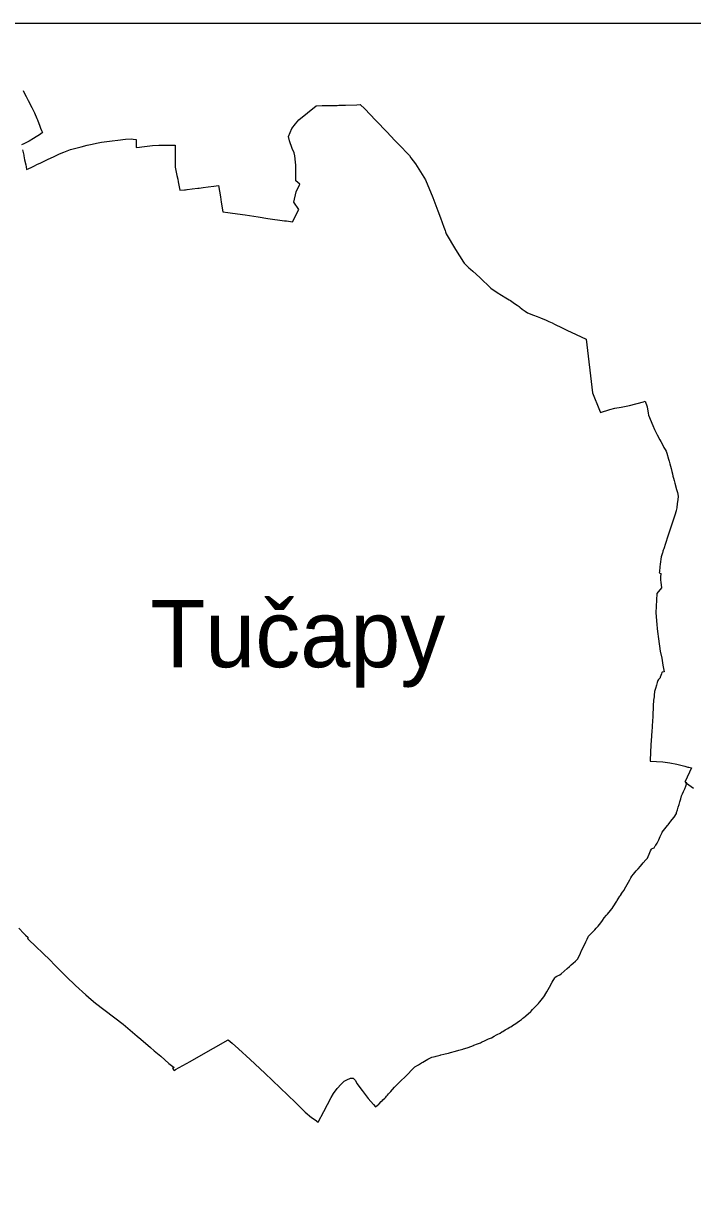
# Model space of a CAD drawing. Extents: x -552716 to -540720, y -1192685 to -1177912.
# Drawn here: x -547852 to -546493, y -1183546 to -1181162 of the extents above; entities that cross this region are included whole.
import ezdxf

# ---------------------------------------------------------------- set-up
doc = ezdxf.new("R2010")
doc.units = 0
doc.layers.add('Vrstva 1', color=7, linetype='Continuous')
doc.layers.add('Vrstva 60', color=7, linetype='Continuous')

msp = doc.modelspace()

# ---------------------------------------------------------------- linework, layer by layer
at = {"layer": 'Vrstva 1'}
for p, q in [((-546507.5, -1182701.9), (-546504.1, -1182704.7)), ((-546505.2, -1182707.5), (-546507.5, -1182701.9)), ((-546504.1, -1182704.7), (-546504.7, -1182705.9)), ((-546514.7, -1182731.2), (-546513.9, -1182728.6)), ((-546513.9, -1182728.6), (-546513.3, -1182727.3)), ((-546513.3, -1182727.3), (-546511, -1182722.2)), ((-546511, -1182722.2), (-546509.7, -1182719.6)), ((-546509.7, -1182719.6), (-546508.5, -1182717)), ((-546508.5, -1182717), (-546506.5, -1182711.8)), ((-546506.5, -1182711.8), (-546505.2, -1182707.5)), ((-546504.7, -1182705.9), (-546490.6, -1182715.5)), ((-546521.8, -1182754.7), (-546520, -1182748.9)), ((-546520, -1182748.9), (-546518.4, -1182743.6)), ((-546518.4, -1182743.6), (-546516.6, -1182737.4)), ((-546516.6, -1182737.4), (-546514.7, -1182731.2)), ((-546536.4, -1182782.7), (-546530.8, -1182775.4)), ((-546530.8, -1182775.4), (-546530.1, -1182774.6)), ((-546530.1, -1182774.6), (-546525.5, -1182767.1)), ((-546525.5, -1182767.1), (-546525, -1182765.5)), ((-546525, -1182765.5), (-546523.3, -1182759.8)), ((-546523.3, -1182759.8), (-546521.8, -1182754.7)), ((-546554.3, -1182805.4), (-546548.8, -1182798.5)), ((-546548.8, -1182798.5), (-546546.1, -1182795.1)), ((-546546.1, -1182795.1), (-546543.2, -1182791.4)), ((-546543.2, -1182791.4), (-546542.4, -1182790.5)), ((-546542.4, -1182790.5), (-546538.4, -1182785.2)), ((-546538.4, -1182785.2), (-546536.4, -1182782.7)), ((-546564, -1182826.5), (-546561.3, -1182820.6)), ((-546561.3, -1182820.6), (-546558.2, -1182814)), ((-546558.2, -1182814), (-546554.5, -1182805.9)), ((-546554.5, -1182805.9), (-546554.3, -1182805.4)), ((-546580.9, -1182850), (-546579.5, -1182846.7)), ((-546579.5, -1182846.7), (-546577.8, -1182843)), ((-546577.8, -1182843), (-546576.1, -1182839.9)), ((-546576.1, -1182839.9), (-546574.6, -1182838.4)), ((-546574.6, -1182838.4), (-546570.4, -1182836.8)), ((-546570.4, -1182836.8), (-546568.2, -1182832.8)), ((-546568.2, -1182832.8), (-546567.4, -1182831.5)), ((-546567.4, -1182831.5), (-546564.5, -1182827.2)), ((-546564.5, -1182827.2), (-546564, -1182826.5)), ((-546598.4, -1182874.2), (-546595.4, -1182870.6)), ((-546595.4, -1182870.6), (-546592.7, -1182867.5)), ((-546592.7, -1182867.5), (-546587.6, -1182861.6)), ((-546587.6, -1182861.6), (-546584.4, -1182857.9)), ((-546584.4, -1182857.9), (-546582.8, -1182854.4)), ((-546582.8, -1182854.4), (-546580.9, -1182850)), ((-546618, -1182898.2), (-546616, -1182894.6)), ((-546616, -1182894.6), (-546612.3, -1182890.3)), ((-546612.3, -1182890.3), (-546606.9, -1182884)), ((-546606.9, -1182884), (-546604.9, -1182881.7)), ((-546604.9, -1182881.7), (-546603.1, -1182879.6)), ((-546603.1, -1182879.6), (-546598.4, -1182874.2)), ((-546631, -1182921.3), (-546625.3, -1182911.2)), ((-546625.3, -1182911.2), (-546620, -1182901.8)), ((-546620, -1182901.8), (-546618, -1182898.2)), ((-546645.7, -1182944.3), (-546643.5, -1182940.9)), ((-546643.5, -1182940.9), (-546640, -1182935.5)), ((-546640, -1182935.5), (-546638.9, -1182933.8)), ((-546638.9, -1182933.8), (-546637.7, -1182931.9)), ((-546637.7, -1182931.9), (-546637.3, -1182931.3)), ((-546637.3, -1182931.3), (-546636, -1182929.2)), ((-546636, -1182929.2), (-546634.7, -1182927.2)), ((-546634.7, -1182927.2), (-546631.8, -1182922.9)), ((-546631.8, -1182922.9), (-546631, -1182921.3)), ((-546665.4, -1182971.9), (-546659.3, -1182964.4)), ((-546659.3, -1182964.4), (-546656.8, -1182961.2)), ((-546656.8, -1182961.2), (-546655.9, -1182960.1)), ((-546655.9, -1182960.1), (-546653.7, -1182956.8)), ((-546653.7, -1182956.8), (-546646.3, -1182945.2)), ((-546646.3, -1182945.2), (-546645.7, -1182944.3)), ((-546684.6, -1182996.5), (-546678.7, -1182989.4)), ((-546678.7, -1182989.4), (-546675.5, -1182984.6)), ((-546675.5, -1182984.6), (-546672.1, -1182979.6)), ((-546672.1, -1182979.6), (-546667.3, -1182974.1)), ((-546667.3, -1182974.1), (-546665.4, -1182971.9)), ((-547861.3, -1183000.1), (-547851.6, -1183011.3)), ((-547851.6, -1183011.3), (-547848.3, -1183014.2)), ((-547848.3, -1183014.2), (-547842.6, -1183019.2)), ((-546703.8, -1183016.3), (-546697.5, -1183009.8)), ((-546697.5, -1183009.8), (-546691.2, -1183003.4)), ((-546691.2, -1183003.4), (-546688.4, -1183000.5)), ((-546688.4, -1183000.5), (-546685.8, -1182997.8)), ((-546685.8, -1182997.8), (-546684.6, -1182996.5)), ((-547842.6, -1183019.2), (-547843.9, -1183021.1)), ((-547843.9, -1183021.1), (-547841.9, -1183023)), ((-547841.9, -1183023), (-547798, -1183065.5)), ((-546715.6, -1183040.9), (-546713.2, -1183035.9)), ((-546713.2, -1183035.9), (-546710.3, -1183030)), ((-546710.3, -1183030), (-546709.5, -1183028.2)), ((-546709.5, -1183028.2), (-546706.7, -1183022.4)), ((-546706.7, -1183022.4), (-546703.8, -1183016.3)), ((-546726.2, -1183063.2), (-546722.5, -1183055.5)), ((-546722.5, -1183055.5), (-546720.3, -1183050.8)), ((-546720.3, -1183050.8), (-546717.9, -1183045.8)), ((-546717.9, -1183045.8), (-546715.6, -1183040.9)), ((-547798, -1183065.5), (-547789.1, -1183075)), ((-547789.1, -1183075), (-547765.2, -1183098.8)), ((-546759.6, -1183093.4), (-546747.4, -1183082.4)), ((-546747.4, -1183082.4), (-546742.9, -1183078.3)), ((-546742.9, -1183078.3), (-546739.2, -1183074.9)), ((-546739.2, -1183074.9), (-546735.3, -1183071.5)), ((-546735.3, -1183071.5), (-546730.4, -1183067.1)), ((-546730.4, -1183067.1), (-546726.2, -1183063.2)), ((-547765.2, -1183098.8), (-547746.7, -1183116.5)), ((-546783.1, -1183119.9), (-546777.7, -1183110.1)), ((-546777.7, -1183110.1), (-546772.7, -1183101.3)), ((-546772.7, -1183101.3), (-546772, -1183100)), ((-546772, -1183100), (-546768.1, -1183097.9)), ((-546768.1, -1183097.9), (-546762.5, -1183094.9)), ((-546762.5, -1183094.9), (-546759.6, -1183093.4)), ((-547746.7, -1183116.5), (-547725.7, -1183136)), ((-546792.4, -1183136.4), (-546790.5, -1183133.1)), ((-546790.5, -1183133.1), (-546788.5, -1183129.4)), ((-546788.5, -1183129.4), (-546785.9, -1183124.9)), ((-546785.9, -1183124.9), (-546783.1, -1183119.9)), ((-547725.7, -1183136), (-547714.4, -1183145)), ((-547714.4, -1183145), (-547705.6, -1183152.7)), ((-547705.6, -1183152.7), (-547649.8, -1183195.1)), ((-546812.1, -1183160.1), (-546808.8, -1183156.6)), ((-546808.8, -1183156.6), (-546805.8, -1183153.4)), ((-546805.8, -1183153.4), (-546803.3, -1183150.8)), ((-546803.3, -1183150.8), (-546802.7, -1183150)), ((-546802.7, -1183150), (-546797.5, -1183143.2)), ((-546797.5, -1183143.2), (-546792.8, -1183137)), ((-546792.8, -1183137), (-546792.4, -1183136.4)), ((-546836, -1183182.3), (-546831.3, -1183178.7)), ((-546831.3, -1183178.7), (-546830.4, -1183178)), ((-546830.4, -1183178), (-546826.4, -1183174.3)), ((-546826.4, -1183174.3), (-546821.2, -1183169.6)), ((-546821.2, -1183169.6), (-546820.7, -1183169)), ((-546820.7, -1183169), (-546817.7, -1183165.9)), ((-546817.7, -1183165.9), (-546814.9, -1183163.1)), ((-546814.9, -1183163.1), (-546813.6, -1183161.8)), ((-546813.6, -1183161.8), (-546812.1, -1183160.1)), ((-547649.8, -1183195.1), (-547621.2, -1183220)), ((-546873, -1183207.2), (-546867.7, -1183204)), ((-546867.7, -1183204), (-546865.2, -1183202.4)), ((-546865.2, -1183202.4), (-546864.1, -1183201.7)), ((-546864.1, -1183201.7), (-546862, -1183200.5)), ((-546862, -1183200.5), (-546858.8, -1183198.6)), ((-546858.8, -1183198.6), (-546858.1, -1183198.1)), ((-546858.1, -1183198.1), (-546855.2, -1183196.1)), ((-546855.2, -1183196.1), (-546851.9, -1183193.9)), ((-546851.9, -1183193.9), (-546848.7, -1183191.8)), ((-546848.7, -1183191.8), (-546844, -1183188.6)), ((-546844, -1183188.6), (-546840.2, -1183185.6)), ((-546840.2, -1183185.6), (-546837.1, -1183183.2)), ((-546837.1, -1183183.2), (-546836, -1183182.3)), ((-547621.2, -1183220), (-547613.7, -1183226.2)), ((-547613.7, -1183226.2), (-547594.2, -1183242.8)), ((-547495.7, -1183261.1), (-547436.1, -1183226.9)), ((-547436.1, -1183226.9), (-547427.9, -1183233.9)), ((-546921.2, -1183232), (-546913.9, -1183228.6)), ((-546913.9, -1183228.6), (-546911.3, -1183227.4)), ((-546911.3, -1183227.4), (-546906.9, -1183225.5)), ((-546906.9, -1183225.5), (-546901.4, -1183223.1)), ((-546901.4, -1183223.1), (-546895.8, -1183220)), ((-546895.8, -1183220), (-546890.9, -1183217.3)), ((-546890.9, -1183217.3), (-546889.4, -1183216.6)), ((-546889.4, -1183216.6), (-546883.5, -1183213.4)), ((-546883.5, -1183213.4), (-546879.8, -1183211.3)), ((-546879.8, -1183211.3), (-546878, -1183210.2)), ((-546878, -1183210.2), (-546873, -1183207.2)), ((-547594.2, -1183242.8), (-547586.5, -1183249.5)), ((-547586.5, -1183249.5), (-547573.2, -1183260.4)), ((-547427.9, -1183233.9), (-547415.3, -1183245.4)), ((-547415.3, -1183245.4), (-547391.3, -1183267.4)), ((-546988.3, -1183254), (-546984.7, -1183253)), ((-546984.7, -1183253), (-546974, -1183250.2)), ((-546974, -1183250.2), (-546967.6, -1183248.4)), ((-546967.6, -1183248.4), (-546959.6, -1183246.1)), ((-546959.6, -1183246.1), (-546958.2, -1183245.6)), ((-546958.2, -1183245.6), (-546950.4, -1183243.2)), ((-546950.4, -1183243.2), (-546948.3, -1183242.5)), ((-546948.3, -1183242.5), (-546937.8, -1183238.6)), ((-546937.8, -1183238.6), (-546937.2, -1183238.3)), ((-546937.2, -1183238.3), (-546929.7, -1183235.5)), ((-546929.7, -1183235.5), (-546923.5, -1183233.1)), ((-546923.5, -1183233.1), (-546921.2, -1183232)), ((-547573.2, -1183260.4), (-547556.5, -1183275.5)), ((-547556.5, -1183275.5), (-547546, -1183283.2)), ((-547543.1, -1183287.8), (-547513.4, -1183271.3)), ((-547513.4, -1183271.3), (-547495.7, -1183261.1)), ((-547391.3, -1183267.4), (-547362, -1183294.8)), ((-547049.3, -1183277.7), (-547047.2, -1183276.4)), ((-547047.2, -1183276.4), (-547043.4, -1183274)), ((-547043.4, -1183274), (-547040.8, -1183272.4)), ((-547040.8, -1183272.4), (-547030.6, -1183266.8)), ((-547030.6, -1183266.8), (-547026.2, -1183264.5)), ((-547026.2, -1183264.5), (-547024, -1183263.2)), ((-547024, -1183263.2), (-547022, -1183262.7)), ((-547022, -1183262.7), (-547015.8, -1183261)), ((-547015.8, -1183261), (-547013.6, -1183260.5)), ((-547013.6, -1183260.5), (-547005.6, -1183258.4)), ((-547005.6, -1183258.4), (-547003.8, -1183258)), ((-547003.8, -1183258), (-546997.9, -1183256.5)), ((-546997.9, -1183256.5), (-546995.2, -1183255.9)), ((-546995.2, -1183255.9), (-546991.7, -1183254.9)), ((-546991.7, -1183254.9), (-546988.3, -1183254)), ((-547546, -1183283.2), (-547549.4, -1183285.8)), ((-547549.4, -1183285.8), (-547545.8, -1183289.3)), ((-547545.8, -1183289.3), (-547543.1, -1183287.8)), ((-547362, -1183294.8), (-547314.6, -1183340)), ((-547077.5, -1183302.9), (-547070.6, -1183296)), ((-547070.6, -1183296), (-547063.5, -1183289)), ((-547063.5, -1183289), (-547056.8, -1183282.3)), ((-547056.8, -1183282.3), (-547049.3, -1183277.7)), ((-547214.4, -1183326), (-547206.3, -1183317.1)), ((-547206.3, -1183317.1), (-547200.3, -1183311.1)), ((-547200.3, -1183311.1), (-547195, -1183308.4)), ((-547195, -1183308.4), (-547187.9, -1183305.1)), ((-547187.9, -1183305.1), (-547183.9, -1183304.9)), ((-547183.9, -1183304.9), (-547181.9, -1183305.3)), ((-547181.9, -1183305.3), (-547179.6, -1183307.9)), ((-547179.6, -1183307.9), (-547178.1, -1183309.5)), ((-547178.1, -1183309.5), (-547174, -1183316.5)), ((-547174, -1183316.5), (-547172.6, -1183318.9)), ((-547172.6, -1183318.9), (-547163.6, -1183329.9)), ((-547102.1, -1183327.9), (-547098.2, -1183323.7)), ((-547098.2, -1183323.7), (-547096.3, -1183321.5)), ((-547096.3, -1183321.5), (-547084.4, -1183309.7)), ((-547084.4, -1183309.7), (-547077.5, -1183302.9)), ((-547314.6, -1183340), (-547299.6, -1183354.7)), ((-547241.6, -1183372.7), (-547226.7, -1183344.4)), ((-547226.7, -1183344.4), (-547221.9, -1183336.6)), ((-547221.9, -1183336.6), (-547214.4, -1183326)), ((-547163.6, -1183329.9), (-547152, -1183346.5)), ((-547152, -1183346.5), (-547140.6, -1183358.9)), ((-547121.6, -1183349.2), (-547117.9, -1183345.6)), ((-547117.9, -1183345.6), (-547116.1, -1183343.9)), ((-547116.1, -1183343.9), (-547114.3, -1183341.8)), ((-547114.3, -1183341.8), (-547112.4, -1183339.6)), ((-547112.4, -1183339.6), (-547110.3, -1183337.1)), ((-547110.3, -1183337.1), (-547106.6, -1183332.8)), ((-547106.6, -1183332.8), (-547105.8, -1183331.9)), ((-547105.8, -1183331.9), (-547102.8, -1183328.6)), ((-547102.8, -1183328.6), (-547102.1, -1183327.9)), ((-547299.6, -1183354.7), (-547279.8, -1183374.2)), ((-547253, -1183394.4), (-547241.6, -1183372.7)), ((-547140.6, -1183358.9), (-547136.5, -1183363.3)), ((-547136.5, -1183363.3), (-547133.4, -1183360.7)), ((-547133.4, -1183360.7), (-547130, -1183357.7)), ((-547130, -1183357.7), (-547129.4, -1183357.1)), ((-547129.4, -1183357.1), (-547125, -1183352.7)), ((-547125, -1183352.7), (-547123.2, -1183350.9)), ((-547123.2, -1183350.9), (-547121.6, -1183349.2)), ((-547279.8, -1183374.2), (-547266.6, -1183384.8)), ((-547266.6, -1183384.8), (-547259.7, -1183389.7)), ((-547259.7, -1183389.7), (-547253, -1183394.4))]:
    msp.add_line(p, q, dxfattribs=at)
for points in [[(-547852.6, -1181297.8), (-547850.4, -1181302.4), (-547846.6, -1181309.9), (-547842.3, -1181318.2), (-547835.4, -1181332.1), (-547830.3, -1181342.2), (-547830, -1181343), (-547824.9, -1181354.5), (-547823.7, -1181357.3), (-547820.7, -1181365.2), (-547819.5, -1181368.3), (-547817.2, -1181374.1), (-547815.2, -1181379.4), (-547814.1, -1181382.2), (-547813.6, -1181383.5), (-547817.7, -1181386.5), (-547831.9, -1181395.7), (-547840.5, -1181401), (-547851.3, -1181406.3), (-547856, -1181408)], [(-547298.9, -1181465.3), (-547298.9, -1181449.7), (-547299.3, -1181443.7), (-547301, -1181430.6), (-547302.1, -1181424.7), (-547305.8, -1181415.8), (-547311.3, -1181399.9), (-547313.9, -1181391.6), (-547306.6, -1181375.1), (-547299.5, -1181365.7), (-547292.5, -1181357.4), (-547257.3, -1181329.1), (-547245.5, -1181328.7), (-547214.6, -1181328.1), (-547211, -1181328), (-547197.6, -1181327.5), (-547174.8, -1181327.1), (-547168.1, -1181326.6), (-547158.8, -1181335.4), (-547137.1, -1181358.3), (-547112.7, -1181383.4), (-547107.3, -1181389.1), (-547096.3, -1181400.6), (-547082.9, -1181414.3), (-547075.2, -1181422.2), (-547067.4, -1181430.3), (-547064.8, -1181434.6), (-547055.6, -1181447.2), (-547045.3, -1181463.1), (-547035.5, -1181479.2), (-547020.3, -1181515.4), (-547016.2, -1181525.9), (-547010, -1181542.3), (-547004.7, -1181556.6), (-546997.8, -1181575.7), (-546995.4, -1181582.3), (-546994.3, -1181585.4), (-546992.9, -1181589.2), (-546974.1, -1181620.9), (-546957.7, -1181647.1), (-546956.4, -1181648.7), (-546954.6, -1181650.8), (-546953.3, -1181652.3), (-546947.8, -1181657.9), (-546946.9, -1181658.6), (-546943.7, -1181661.1), (-546938.7, -1181665), (-546924.7, -1181678.1), (-546902.5, -1181699.4), (-546889.5, -1181708.1), (-546871.9, -1181719.4), (-546865.3, -1181723.2), (-546864, -1181723.9), (-546862.8, -1181724.7), (-546860, -1181726.6), (-546854.3, -1181730.5), (-546848.9, -1181734.4), (-546845, -1181737.2), (-546843.3, -1181738.4), (-546838.5, -1181742), (-546832.4, -1181746.6), (-546827.8, -1181750), (-546815.7, -1181754.4), (-546808.1, -1181757.2), (-546801.7, -1181759.6), (-546789.7, -1181764.9), (-546784.5, -1181767.3), (-546778, -1181770.3), (-546773.1, -1181772.6), (-546766.5, -1181775.9), (-546764.3, -1181777), (-546756.2, -1181780.8), (-546751.8, -1181782.9), (-546748, -1181784.7), (-546729.1, -1181793.7), (-546708.7, -1181803.4), (-546696, -1181912.3), (-546681.9, -1181947.5), (-546679.8, -1181952.6), (-546660.8, -1181946.2), (-546650.6, -1181943.5), (-546637.3, -1181941.4), (-546620.4, -1181938.1), (-546592.5, -1181930.4), (-546588.6, -1181929.3), (-546584.7, -1181941), (-546582.9, -1181953.6), (-546582.1, -1181957.6), (-546573.6, -1181978.8), (-546570, -1181987.1), (-546564.2, -1181997.7), (-546558.9, -1182007.6), (-546557.1, -1182011), (-546553.1, -1182018.7), (-546550.7, -1182023.1), (-546548.5, -1182027.2)], [(-547853.8, -1181418.5), (-547851.7, -1181429.1), (-547851.4, -1181430.6), (-547849.7, -1181439.1), (-547847.6, -1181449.2), (-547846.8, -1181453.1), (-547846, -1181458.7), (-547836.7, -1181454.4), (-547831, -1181451.7), (-547823.3, -1181447.9), (-547818.1, -1181445.4), (-547802.2, -1181437.4), (-547791.2, -1181432.5), (-547778.6, -1181426.9), (-547770.4, -1181423.4), (-547756.6, -1181418), (-547734.8, -1181412.3), (-547722.5, -1181409.2), (-547715.9, -1181407.6), (-547712.7, -1181406.9), (-547703.6, -1181405), (-547693.7, -1181403.1), (-547671.6, -1181400.2), (-547660.1, -1181398.9), (-547645.1, -1181397), (-547633.5, -1181395.9), (-547629.1, -1181397), (-547623.3, -1181397.6), (-547623.2, -1181410.5), (-547623.2, -1181413.8), (-547616.5, -1181413.2), (-547611.3, -1181412.7), (-547590.1, -1181409.8), (-547577, -1181409), (-547572.4, -1181408.7), (-547543.8, -1181408.8), (-547543.7, -1181453.7), (-547540.3, -1181470.3), (-547538.7, -1181478.3), (-547537.6, -1181483.7), (-547534.5, -1181500.7), (-547525.2, -1181499.7), (-547522.9, -1181499.5), (-547520.4, -1181499.2), (-547519.4, -1181499.1), (-547509.6, -1181497.9), (-547498, -1181496.4), (-547494.8, -1181496.1), (-547486.7, -1181494.9), (-547476.7, -1181493.6), (-547465.6, -1181492.1), (-547455.5, -1181490.7), (-547451.9, -1181514.3), (-547450.2, -1181524.8), (-547446.9, -1181544.6), (-547436.8, -1181546.1), (-547427.7, -1181547.5), (-547401.7, -1181550.9), (-547375.4, -1181554.7), (-547355.6, -1181557.8), (-547321.7, -1181562.5), (-547317.8, -1181563), (-547305.6, -1181564.5), (-547292.4, -1181539.4), (-547302.5, -1181524.9), (-547298.3, -1181504.1), (-547290.8, -1181488.4), (-547298.8, -1181481.7), (-547298.9, -1181465.3)], [(-546548.5, -1182027.2), (-546546.5, -1182030.9), (-546544.5, -1182034.9), (-546541.2, -1182047), (-546540.1, -1182051.4), (-546538.8, -1182056.4), (-546537.4, -1182061.5), (-546536.2, -1182066.2), (-546534.8, -1182071.9), (-546533.5, -1182076.8), (-546532.3, -1182081.4), (-546531.2, -1182085.5), (-546529.8, -1182090.8), (-546528.5, -1182095.7), (-546525.2, -1182108.6), (-546523.4, -1182115.2), (-546521.6, -1182122.2), (-546522.6, -1182129.7), (-546523.6, -1182137.2), (-546524.8, -1182146), (-546525.6, -1182151.5), (-546525.7, -1182152.3), (-546528.6, -1182161.1), (-546533.9, -1182177.4), (-546537.9, -1182189.3), (-546540, -1182195.7), (-546542.5, -1182203.5), (-546547.4, -1182218.2), (-546551, -1182229.3), (-546552, -1182232.1), (-546552.7, -1182234.4), (-546553.2, -1182235.9), (-546553.8, -1182237.7), (-546556.4, -1182245.6), (-546556.4, -1182246), (-546557, -1182249.9), (-546557.1, -1182250.5), (-546557.8, -1182255.5), (-546558.5, -1182260.4), (-546559, -1182265.7), (-546559.9, -1182275.6), (-546560.1, -1182277.9), (-546557.2, -1182279.8), (-546557.5, -1182286.9), (-546557.7, -1182292.9), (-546557.3, -1182296.8), (-546555.9, -1182308.9), (-546565.2, -1182320.4), (-546565.6, -1182334), (-546566.3, -1182346.1), (-546567.2, -1182359.6), (-546565.2, -1182382.9), (-546564.7, -1182391.4), (-546563.8, -1182397.4), (-546561.9, -1182412.2), (-546558.1, -1182437), (-546555.2, -1182451.6), (-546553.2, -1182465.7), (-546550.3, -1182479), (-546554.4, -1182480.1), (-546554.7, -1182480.9), (-546555.6, -1182483.3), (-546558.2, -1182490.4), (-546558.5, -1182491.2), (-546561.5, -1182494.9), (-546563.4, -1182497.2), (-546563.9, -1182498.8), (-546564.4, -1182500.8), (-546565.8, -1182506.3), (-546567.7, -1182513), (-546569.8, -1182519.3), (-546570.4, -1182526.6), (-546570.6, -1182528.2), (-546570.7, -1182530.2), (-546571.7, -1182537.2), (-546571.8, -1182538.7), (-546572.3, -1182546.4), (-546572.5, -1182550.3), (-546572.5, -1182551), (-546573.2, -1182566.8), (-546573.4, -1182570.2), (-546574.6, -1182588.8), (-546574.8, -1182592.4), (-546575.2, -1182599.5), (-546575.8, -1182609.3), (-546575.9, -1182610.1), (-546577.4, -1182627.8), (-546578.1, -1182643), (-546578.1, -1182643.3), (-546578.7, -1182658.6), (-546578.8, -1182661.2), (-546552.8, -1182662.4), (-546538.9, -1182664.6), (-546524.4, -1182666.9), (-546513.8, -1182669.8), (-546508.4, -1182671.2)], [(-546508.4, -1182671.2), (-546502.1, -1182673), (-546500.4, -1182673.4), (-546497.3, -1182674), (-546494.6, -1182674.6), (-546507.5, -1182701.9)]]:
    msp.add_lwpolyline(points, dxfattribs=at)
at = {"layer": 'Vrstva 60'}
msp.add_lwpolyline([(-543896.1, -1181161.6), (-549696, -1181161.6), (-549696, -1188366.4), (-543896.1, -1188366.4)], close=True, dxfattribs=at)

# ---------------------------------------------------------------- texts
at = {"layer": 'Vrstva 1'}
msp.add_text('Tučapy', height=136.69, dxfattribs=at).set_placement((-547594.4, -1182470))

doc.saveas('drawing.dxf')
